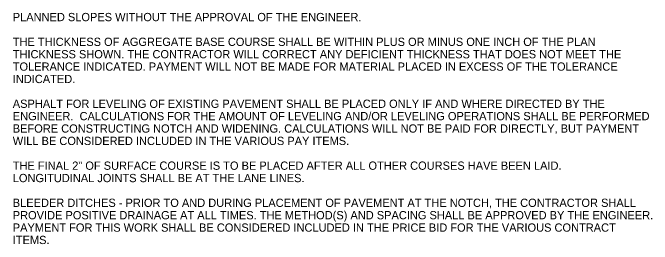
# Model space of a CAD drawing. Extents: x 1461846 to 1462006, y 1686171 to 1686805.
# Drawn here: x 1461850.66 to 1461897.18, y 1686312.6 to 1686329.42 of the extents above; entities that cross this region are included whole.
import ezdxf

# ---------------------------------------------------------------- set-up
doc = ezdxf.new("R2010")
doc.units = 0
doc.layers.add('R_Draft', color=7, linetype='Continuous')

msp = doc.modelspace()

# ---------------------------------------------------------------- texts
at = {"layer": 'R_Draft'}
for s, p in [('PLANNED SLOPES WITHOUT THE APPROVAL OF THE ENGINEER.', (1461850.662, 1686328.811)), ('THE THICKNESS OF AGGREGATE BASE COURSE SHALL BE WITHIN PLUS OR MINUS ONE INCH OF THE PLAN ', (1461850.662, 1686327.011)), ('THICKNESS SHOWN. THE CONTRACTOR WILL CORRECT ANY DEFICIENT THICKNESS THAT DOES NOT MEET THE ', (1461850.662, 1686326.111)), ('TOLERANCE INDICATED. PAYMENT WILL NOT BE MADE FOR MATERIAL PLACED IN EXCESS OF THE TOLERANCE ', (1461850.662, 1686325.211)), ('INDICATED.', (1461850.662, 1686324.311)), ('ASPHALT FOR LEVELING OF EXISTING PAVEMENT SHALL BE PLACED ONLY IF AND WHERE DIRECTED BY THE ', (1461850.662, 1686322.511)), ('ENGINEER.  CALCULATIONS FOR THE AMOUNT OF LEVELING AND/OR LEVELING OPERATIONS SHALL BE PERFORMED ', (1461850.662, 1686321.611)), ('BEFORE CONSTRUCTING NOTCH AND WIDENING. CALCULATIONS WILL NOT BE PAID FOR DIRECTLY, BUT PAYMENT ', (1461850.662, 1686320.711)), ('WILL BE CONSIDERED INCLUDED IN THE VARIOUS PAY ITEMS.', (1461850.662, 1686319.811)), ('THE FINAL 2" OF SURFACE COURSE IS TO BE PLACED AFTER ALL OTHER COURSES HAVE BEEN LAID. ', (1461850.662, 1686318.011)), ('LONGITUDINAL JOINTS SHALL BE AT THE LANE LINES.', (1461850.662, 1686317.111)), ('BLEEDER DITCHES - PRIOR TO AND DURING PLACEMENT OF PAVEMENT AT THE NOTCH, THE CONTRACTOR SHALL ', (1461850.662, 1686315.311)), ('PROVIDE POSITIVE DRAINAGE AT ALL TIMES. THE METHOD(S) AND SPACING SHALL BE APPROVED BY THE ENGINEER. ', (1461850.662, 1686314.411)), ('PAYMENT FOR THIS WORK SHALL BE CONSIDERED INCLUDED IN THE PRICE BID FOR THE VARIOUS CONTRACT ', (1461850.662, 1686313.511)), ('ITEMS.', (1461850.662, 1686312.611))]:
    msp.add_text(s, height=0.6, dxfattribs=at).set_placement(p)

doc.saveas('drawing.dxf')
